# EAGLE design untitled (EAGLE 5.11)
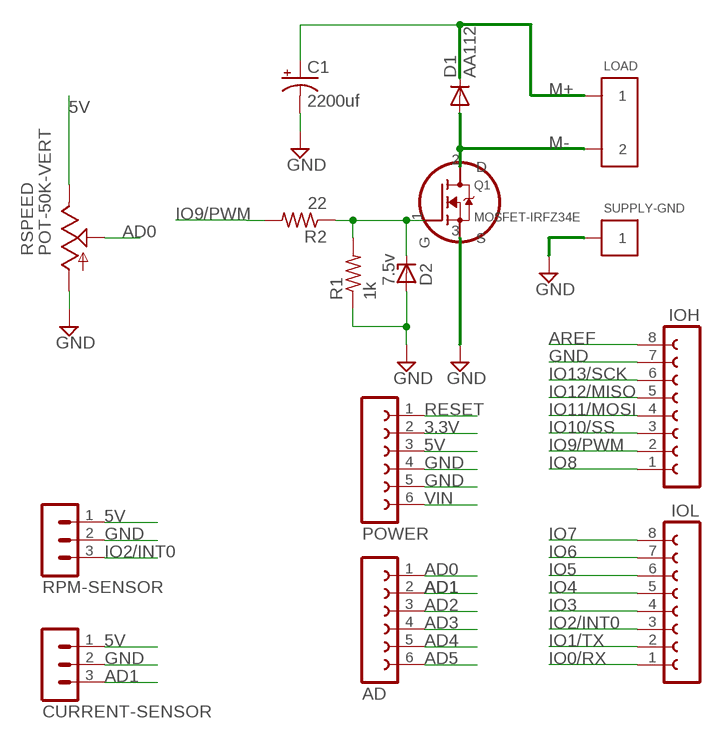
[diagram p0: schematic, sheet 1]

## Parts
AD  FE06-1  [FE06]
C1  2200uf  CPOL-USE7.5-16  [E7,5-16]
CURRENT-SENSOR  MA03-1  [MA03-1]
D1  AA112  [DO07]
D2  7.5v  ZENER-DIODEDO34-7  [DO34Z7]
IOH  FE08-1  [FE08]
IOL  FE08-1  [FE08]
LOAD  SCREW-CLAMP-1.5  [SCREW-CLAMP-1.5]
POWER  FE06-1  [FE06]
Q1  MOSFET-IRFZ34E  [TO220AB]
R1  1k  R-US_0309/10  [0309/10]
R2  22  R-US_0309/10  [0309/10]
RPM-SENSOR  MA03-1  [MA03-1]
RSPEED  POT-50K-VERT  [POT-50K-VERT]
SUPPLY-GND  SCREW-CLAMP-SINGLE  [SCREW-CLAMP-SINGLE]

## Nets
3.3V: POWER.2
5V: CURRENT-SENSOR.1 POWER.3 RPM-SENSOR.1 RSPEED.P$3(E)
AD0: AD.1 RSPEED.P$2(S)
AD1: AD.2 CURRENT-SENSOR.3
AD2: AD.3
AD3: AD.4
AD4: AD.5
AD5: AD.6
AREF: IOH.8
GND: C1.- CURRENT-SENSOR.2 D2.A IOH.7 POWER.4 POWER.5 Q1.3(S) R1.1 RPM-SENSOR.2 RSPEED.P$1(A) SUPPLY-GND.1
IO0/RX: IOL.1
IO1/TX: IOL.2
IO2/INT0: IOL.3 RPM-SENSOR.3
IO3: IOL.4
IO4: IOL.5
IO5: IOL.6
IO6: IOL.7
IO7: IOL.8
IO8: IOH.1
IO9/PWM: IOH.2 R2.2
IO10/SS: IOH.3
IO11/MOSI: IOH.4
IO12/MISO: IOH.5
IO13/SCK: IOH.6
M+: C1.+ D1.C LOAD.1
M-: D1.A LOAD.2 Q1.2(D)
N$2: D2.C Q1.1(G) R1.2 R2.1
RESET: POWER.1
VIN: POWER.6

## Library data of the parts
AD POWER = con-lsta:FE06-1: FEMALE HEADER; OC_FARNELL: unknown; OC_NEWARK: unknown
C1 = rcl:CPOL-US: POLARIZED CAPACITOR, American symbol
CURRENT-SENSOR RPM-SENSOR = con-lstb:MA03-1: PIN HEADER; OC_FARNELL: unknown; OC_NEWARK: unknown
D1 = diode:AA112: DIODE
D2 = diode:ZENER-DIODE: Z-Diode
IOH IOL = con-lsta:FE08-1: FEMALE HEADER; OC_FARNELL: unknown; OC_NEWARK: unknown
LOAD = trl:SCREW-CLAMP-1.5
Q1 = trl:MOSFET-IRFZ34E
R1 R2 = resistor:R-US_: RESISTOR, American symbol
RSPEED = trl:POT-50K-VERT
SUPPLY-GND = trl:SCREW-CLAMP-SINGLE

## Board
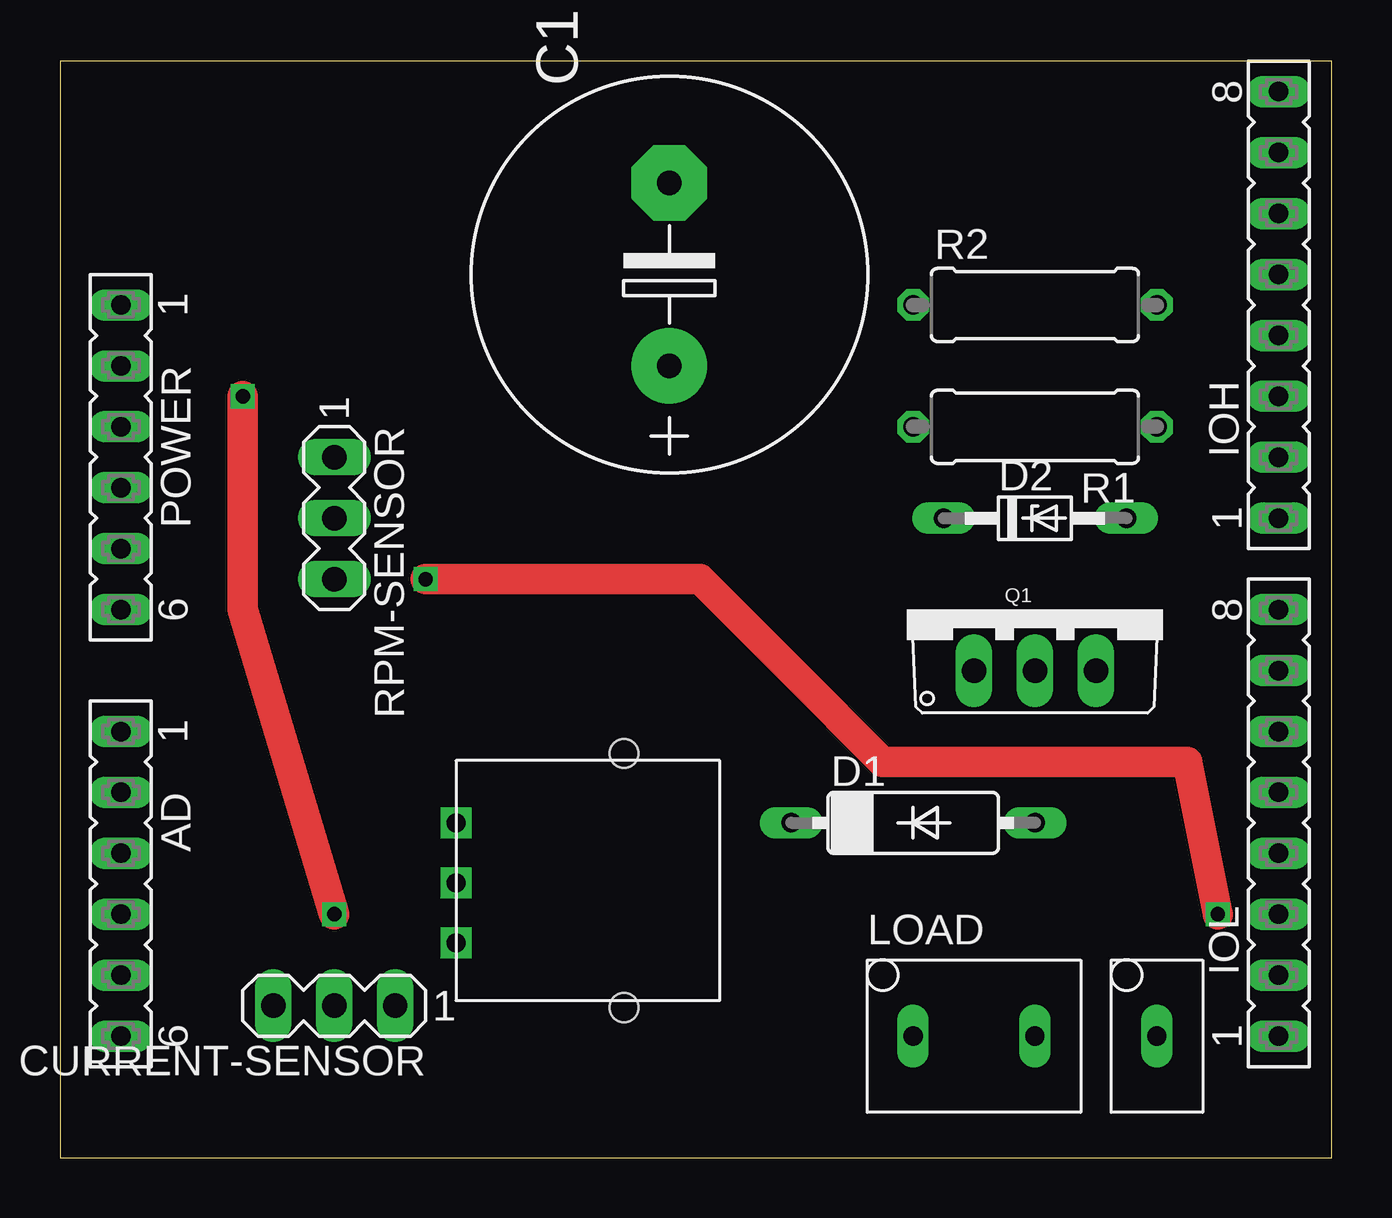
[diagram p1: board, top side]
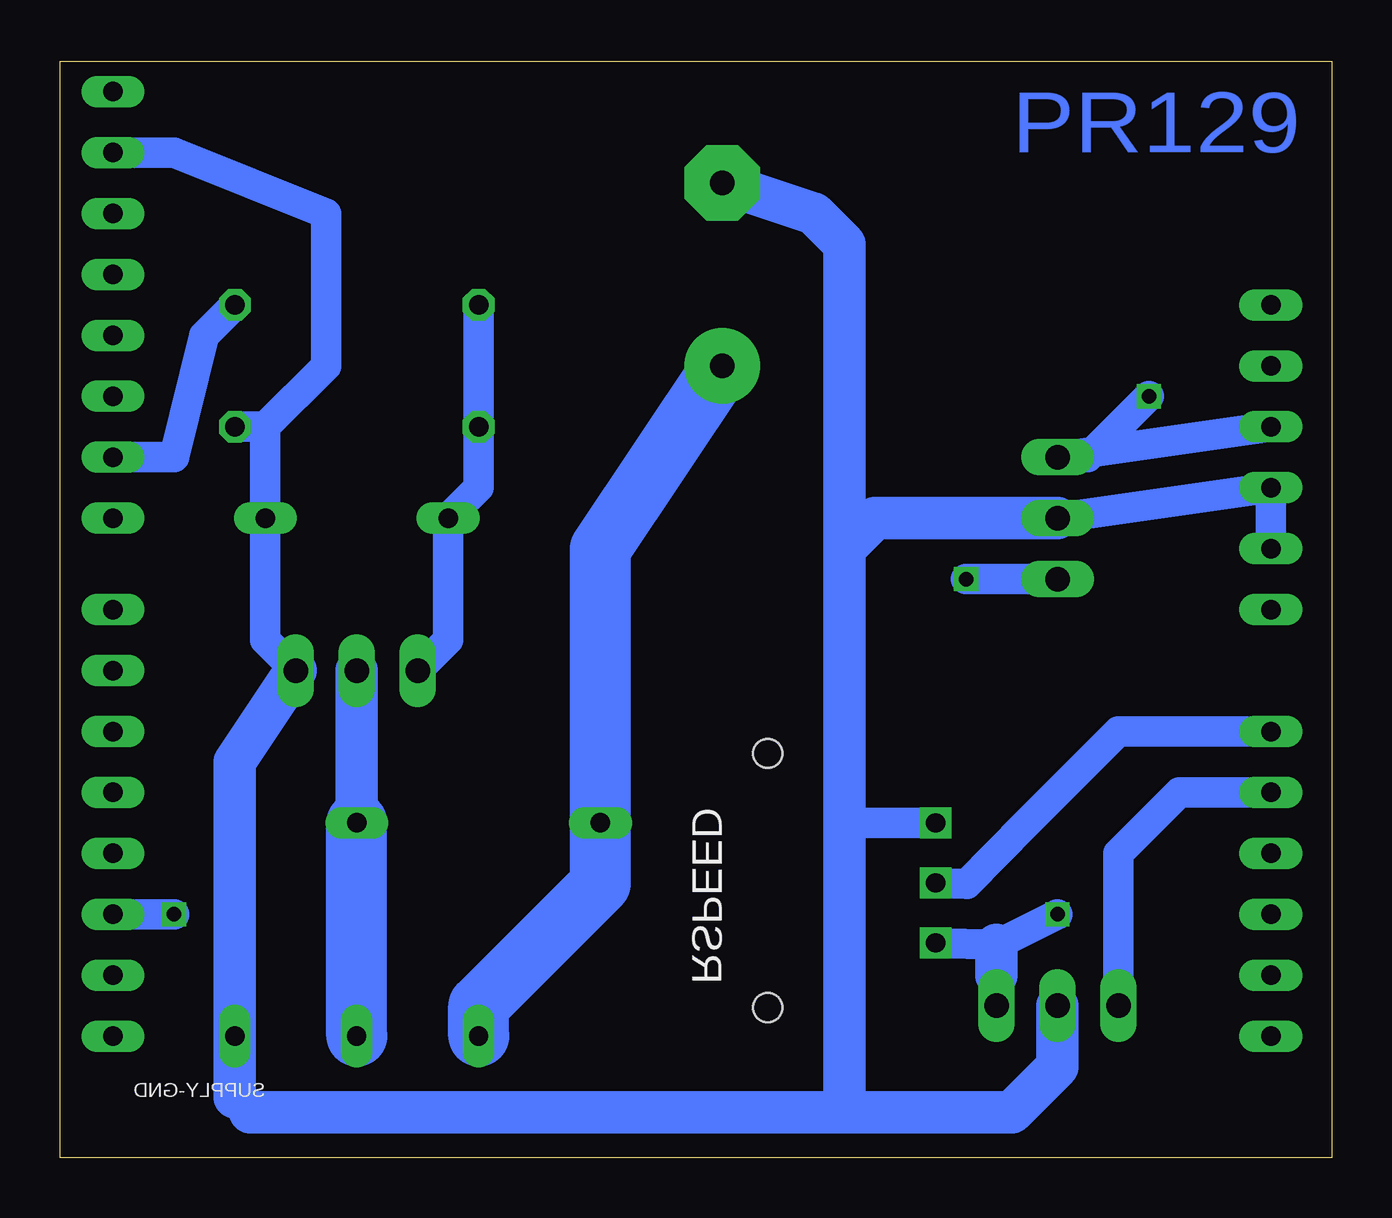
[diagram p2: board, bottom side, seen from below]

Size 53.01 x 45.71 mm. Coordinates in mm from the lower left corner, seen from the top.
Outline: 0,0 53.01,0 53.01,45.71 0,45.71 0,0
Copper layers (1*16): Top 0.035mm / dielectric 1.5mm / Bottom 0.035mm
Design rules "default": minimum track width 10mil, minimum drill 24mil, track to track 8mil, track to pad 8mil, pad to pad 8mil, via to via 8mil, smd to smd 8mil, copper to edge 40mil, drill to drill 8mil, minimum pad ring 10mil, minimum via ring 8mil, stop-mask expansion 4mil, vias tented up to drill 0mil, thermal gap 10mil

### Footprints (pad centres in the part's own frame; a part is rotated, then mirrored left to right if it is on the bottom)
FE06 = drill 0.813 long: 1 -6.35,0; 2 -3.81,0; 3 -1.27,0; 4 1.27,0; 5 3.81,0; 6 6.35,0
E7,5-16 = drill 1.016 pad 3.15 round: + -3.81,0 | drill 1.016 pad 3.15 octagon: - 3.81,0
MA03-1 = drill 1.016 long: 1 -2.54,0; 2 0,0; 3 2.54,0
DO07 = drill 0.813 long: A 5.08,0; C -5.08,0
DO34Z7 = drill 0.813 long: A 3.81,0; C -3.81,0
FE08 = drill 0.813 long: 1 -8.89,0; 2 -6.35,0; 3 -3.81,0; 4 -1.27,0; 5 1.27,0; 6 3.81,0; 7 6.35,0; 8 8.89,0
SCREW-CLAMP-1.5 = drill 0.8 long: 1 -1.27,0; 2 3.81,0
TO220AB = drill 1.016 long: 1 -2.54,0; 2 0,0; 3 2.54,0
0309/10 = drill 0.813 octagon: 1 -5.08,0; 2 5.08,0
POT-50K-VERT = drill 0.8 square: P$1 -2.54,-5.08; P$2 -0.04,-5.08; P$3 2.46,-5.08 | hole 1.2: -5.44,1.92; 5.16,1.92
SCREW-CLAMP-SINGLE = drill 0.8 long: 1 -1.27,0

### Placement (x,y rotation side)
AD  2.54,11.43 270 top
C1  25.4,36.83 90 top
CURRENT-SENSOR  11.43,6.35 180 top
D1  35.56,13.97 0 top
D2  40.64,26.67 0 top
IOH  50.8,35.56 90 top
IOL  50.8,13.97 90 top
LOAD  36.83,5.08 0 top
POWER  2.54,29.21 270 top
Q1  40.64,20.32 0 top
R1  40.64,30.48 180 top
R2  40.64,35.56 0 top
RPM-SENSOR  11.43,26.67 270 top
RSPEED  21.59,11.43 270 top
SUPPLY-GND  46.99,5.08 0 top

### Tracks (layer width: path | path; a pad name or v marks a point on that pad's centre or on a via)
5V  (via drill 0.6)
  Top 1.27: v7.62,31.75 7.62,22.86 v11.43,10.16
  Bottom 1.27: CURRENT-SENSOR.1 13.97,7.62 | RSPEED.P$3 13.97,8.89 v11.43,10.16 | POWER.3 RPM-SENSOR.1 10.16,29.21 v7.62,31.75
  Bottom 1.778: 13.97,7.62 13.97,8.89
AD0
  Bottom 1.27: AD.1 8.89,17.78 12.7,13.97 15.2,11.43 RSPEED.P$2
AD1
  Bottom 1.27: CURRENT-SENSOR.3 8.89,12.7 6.35,15.24 AD.2
GND
  Bottom 1.27: Q1.3 44.45,21.59 D2.A 44.45,30.48 | RPM-SENSOR.2 POWER.4 POWER.5 | 45.09,1.91 45.72,2.54 | 20.32,13.97 RSPEED.P$1 | IOH.7 48.26,41.91 41.91,39.37 41.91,33.02 44.45,30.48 | 44.45,30.48 R1.1
  Bottom 1.778: Q1.3 45.72,16.51 SUPPLY-GND.1 45.72,2.54 | CURRENT-SENSOR.2 11.43,3.81 13.34,1.91 20.32,1.91 | 20.32,1.91 45.09,1.91 | 20.32,1.91 20.32,13.97 20.32,25.4 | RPM-SENSOR.2 19.05,26.67 20.32,25.4 | 20.32,25.4 20.32,38.1 21.59,39.37 C1.-
IO2/INT0  (via drill 0.6)
  Top 1.27: v48.26,10.16 46.99,16.51 34.29,16.51 30.48,20.32 26.67,24.13 v15.24,24.13
  Bottom 1.27: IOL.3 v48.26,10.16 | v15.24,24.13 RPM-SENSOR.3
IO9/PWM
  Bottom 1.27: IOH.2 48.26,29.21 46.99,34.29 R2.2
M+
  Bottom 2.54: LOAD.1 35.56,6.35 30.48,11.43 D1.C 30.48,25.4 C1.+
M-
  Bottom 1.778: D1.A Q1.2
  Bottom 2.54: LOAD.2 D1.A
N$2
  Bottom 1.27: R2.1 R1.2 35.56,27.94 D2.C 36.83,21.59 Q1.1

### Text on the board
Bottom: PR129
